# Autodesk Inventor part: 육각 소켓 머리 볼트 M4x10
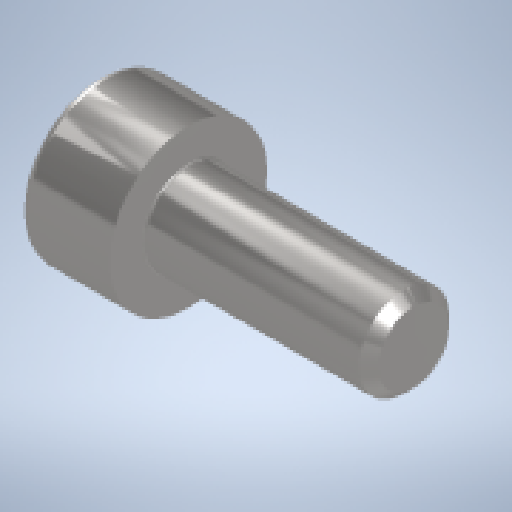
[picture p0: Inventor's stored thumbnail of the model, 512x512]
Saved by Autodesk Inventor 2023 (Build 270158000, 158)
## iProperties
Created: 2024-09
Part Number: 육각 소켓 머리 볼트 M4x10
Material: 강철, 연강
Description: 6각머리 태핑 나사
Document SubType Name: Modeling
Designer: home
Density: 7.85 g/cm^3
Appearance: 기본값
Author: jhkim
Sending System: Autodesk Inventor 2025
Preprocessor: ST-DEVELOPER v20
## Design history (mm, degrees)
node "육각 소켓 머리 볼트 M4x101"
node "솔리드1"
body "Solid1"
